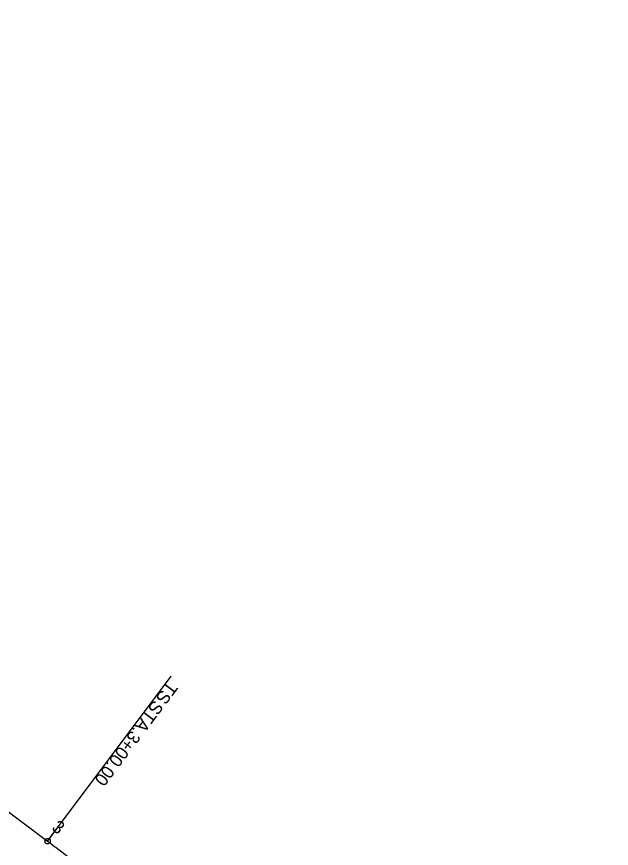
# Model space of a CAD drawing. Extents: x 1323137 to 1326838, y 458936 to 461644.
# Drawn here: x 1324444.6 to 1324574.4, y 460688.4 to 460869.9 of the extents above; entities that cross this region are included whole.
import ezdxf

# ---------------------------------------------------------------- set-up
doc = ezdxf.new("R2010")
doc.units = 0
for name, color, linetype in [('_CIVIL_CONSTRUCTION', 7, 'Continuous'), ('CM_Corridor_Range_Final', 7, 'Continuous'), ('Default', 7, 'Continuous'), ('MD_P_Surface_Asphalt_Concrete_Intermediate_Course', 7, 'Continuous'), ('SN_P_Signs', 7, 'Continuous'), ('SN_X_Public', 7, 'Continuous')]:
    doc.layers.add(name, color=color, linetype=linetype)

msp = doc.modelspace()

# ---------------------------------------------------------------- linework, layer by layer
at = {"layer": '_CIVIL_CONSTRUCTION'}
msp.add_line((1324451.31, 460690.01), (1324478.29, 460726.02), dxfattribs=at)
msp.add_circle((1324451.31, 460690.01), 0.6, dxfattribs=at)
at = {"layer": 'CM_Corridor_Range_Final'}
msp.add_line((1324451.31, 460690), (1324452.51, 460691.6), dxfattribs=at)
at = {"layer": 'Default'}
msp.add_open_spline([(1324451.31, 460690.01), (1324454.64, 460687.51), (1324461.31, 460682.51), (1324474.66, 460672.54), (1324491.41, 460660.14), (1324511.67, 460645.5), (1324532.19, 460631.21), (1324549.56, 460619.71), (1324563.66, 460610.81), (1324570.77, 460606.48), (1324574.35, 460604.34)], degree=3, dxfattribs=at)
at = {"layer": 'MD_P_Surface_Asphalt_Concrete_Intermediate_Course'}
msp.add_line((1324451.31, 460690.01), (1324478.29, 460726.02), dxfattribs=at)
msp.add_circle((1324451.31, 460690.01), 0.6, dxfattribs=at)
at = {"layer": 'SN_P_Signs'}
msp.add_line((1324211.24, 460869.9), (1324451.31, 460690.01), dxfattribs=at)
msp.add_open_spline([(1324451.31, 460690.01), (1324454.64, 460687.51), (1324461.31, 460682.51), (1324474.66, 460672.54), (1324491.41, 460660.14), (1324511.67, 460645.5), (1324532.19, 460631.21), (1324549.56, 460619.71), (1324563.66, 460610.81), (1324570.77, 460606.48), (1324574.35, 460604.34)], degree=3, dxfattribs=at)
at = {"layer": 'SN_X_Public'}
msp.add_line((1324451.31, 460690), (1324452.03, 460690.96), dxfattribs=at)

# ---------------------------------------------------------------- texts
at = {"layer": '_CIVIL_CONSTRUCTION'}
for s, p in [('TS', (1324477.64, 460725.08)), (' STA. ', (1324475.17, 460721.79)), ('3+00.00', (1324469.58, 460714.33))]:
    msp.add_text(s, height=2.8, rotation=233.1538, dxfattribs=at).set_placement(p)
at = {"layer": 'CM_Corridor_Range_Final'}
msp.add_text('3', height=2.8, rotation=323.1538, dxfattribs=at).set_placement((1324452.04, 460692.58))
at = {"layer": 'MD_P_Surface_Asphalt_Concrete_Intermediate_Course'}
for s, p in [('TS', (1324477.64, 460725.08)), (' STA. ', (1324475.17, 460721.79)), ('3+00.00', (1324469.58, 460714.33))]:
    msp.add_text(s, height=2.8, rotation=233.1538, dxfattribs=at).set_placement(p)

doc.saveas('drawing.dxf')
